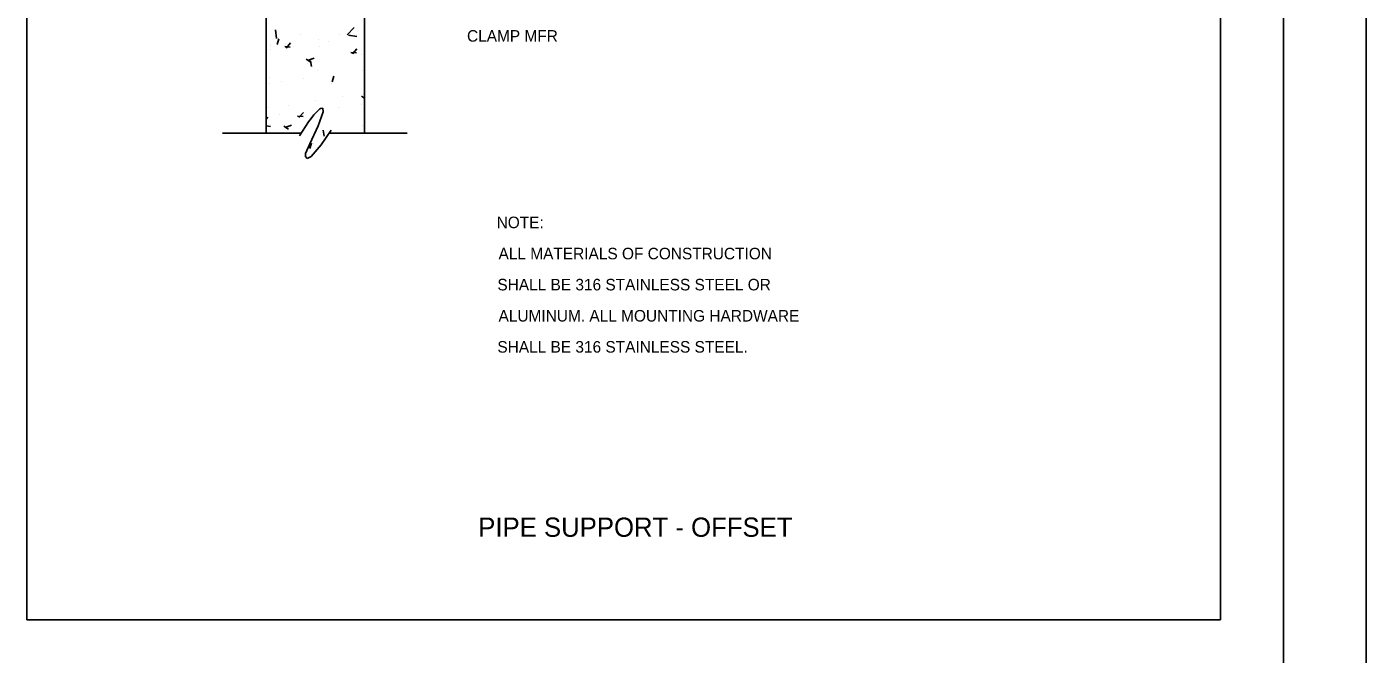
# Model space of a CAD drawing. Extents: x 2147138 to 2147698, y 2147153 to 2147515.
# Drawn here: x 2147558.3 to 2147697.7, y 2147347.7 to 2147412.9 of the extents above; entities that cross this region are included whole.
import ezdxf

# ---------------------------------------------------------------- set-up
doc = ezdxf.new("R2010")
doc.units = 0
for name, color, linetype in [('CONSTRUCTION_CLASS', 7, 'Continuous'), ('G-ANNO-TEXT-LW10', 7, 'Continuous'), ('G-ANNO-TITL', 7, 'Continuous'), ('G-DETL-LW20', 7, 'Continuous'), ('G-DETL-PATT', 7, 'Continuous'), ('PATTERN_CLASS', 7, 'Continuous')]:
    doc.layers.add(name, color=color, linetype=linetype)

msp = doc.modelspace()

# ---------------------------------------------------------------- linework, layer by layer
for p, q in [((2147587.61, 2147403.05), (2147587.89, 2147403.4)), ((2147587.89, 2147403.4), (2147588.18, 2147403.79)), ((2147588.18, 2147403.79), (2147588.48, 2147404.09)), ((2147588.48, 2147404.09), (2147588.78, 2147404.37)), ((2147589.15, 2147404.07), (2147588.62, 2147402.62)), ((2147588.78, 2147404.37), (2147588.81, 2147404.39)), ((2147588.81, 2147404.39), (2147588.85, 2147404.44)), ((2147588.85, 2147404.44), (2147589.11, 2147404.46)), ((2147589.11, 2147404.46), (2147589.15, 2147404.07)), ((2147586.86, 2147401.88), (2147578.67, 2147401.88)), ((2147586.69, 2147401.6), (2147587.61, 2147403.05)), ((2147588.62, 2147402.62), (2147587.75, 2147400.77)), ((2147588.95, 2147400.66), (2147589.98, 2147402.18)), ((2147589.78, 2147401.88), (2147597.87, 2147401.88)), ((2147587.75, 2147400.77), (2147587.31, 2147399.76)), ((2147587.91, 2147399.44), (2147588.95, 2147400.66)), ((2147587.31, 2147399.76), (2147587.29, 2147399.44)), ((2147587.29, 2147399.44), (2147587.47, 2147399.23)), ((2147587.47, 2147399.23), (2147587.91, 2147399.44))]:
    msp.add_line(p, q)
at = {"layer": 'CONSTRUCTION_CLASS'}
for p, q in [((2147697.66, 2147152.81), (2147697.66, 2147515.08)), ((2147689.06, 2147507.94), (2147689.06, 2147160.52))]:
    msp.add_line(p, q, dxfattribs=at)
at = {"layer": 'G-DETL-LW20'}
for p, q in [((2147583.21, 2147401.92), (2147583.21, 2147491.1)), ((2147593.45, 2147491.1), (2147593.45, 2147401.92))]:
    msp.add_line(p, q, dxfattribs=at)
at = {"layer": 'G-DETL-PATT'}
for p, q in [((2147591.63, 2147412.09), (2147592.37, 2147412.87)), ((2147584.28, 2147411.71), (2147584.18, 2147412.62)), ((2147584.35, 2147411.09), (2147584.54, 2147411.67)), ((2147586.77, 2147412.15), (2147586.77, 2147412.15)), ((2147588.63, 2147411.61), (2147588.63, 2147411.61)), ((2147590.8, 2147412.15), (2147590.8, 2147412.15)), ((2147591.78, 2147412.04), (2147592.64, 2147411.91)), ((2147591.9, 2147411.93), (2147591.9, 2147411.93)), ((2147583.64, 2147410.89), (2147583.64, 2147410.89)), ((2147583.64, 2147410.55), (2147583.64, 2147410.55)), ((2147583.67, 2147411.07), (2147583.67, 2147411.07)), ((2147585.15, 2147410.87), (2147585.72, 2147410.82)), ((2147585.2, 2147411.19), (2147585.2, 2147411.19)), ((2147585.3, 2147410.7), (2147585.76, 2147411.25)), ((2147586.04, 2147410.87), (2147586.04, 2147410.87)), ((2147588.79, 2147410.86), (2147588.79, 2147410.86)), ((2147589.68, 2147411.35), (2147589.68, 2147411.35)), ((2147592.03, 2147410.27), (2147592.61, 2147410.22)), ((2147592.18, 2147410.1), (2147592.64, 2147410.65)), ((2147587.39, 2147409.57), (2147587.87, 2147409.25)), ((2147587.5, 2147409.08), (2147587.5, 2147409.08)), ((2147587.53, 2147409.41), (2147588.2, 2147409.67)), ((2147587.92, 2147408.79), (2147587.81, 2147409.39)), ((2147593.1, 2147410.04), (2147593.1, 2147410.04)), ((2147593.44, 2147409.09), (2147593.44, 2147409.09)), ((2147583.52, 2147407.7), (2147583.52, 2147407.7)), ((2147587.15, 2147407.56), (2147587.15, 2147407.56)), ((2147588.51, 2147408.42), (2147588.51, 2147408.42)), ((2147590.08, 2147407.22), (2147590.27, 2147407.8)), ((2147593.22, 2147408.36), (2147593.22, 2147408.36)), ((2147583.52, 2147407.08), (2147583.52, 2147407.08)), ((2147584.86, 2147407.27), (2147584.86, 2147407.27)), ((2147589.99, 2147407.05), (2147589.99, 2147407.05)), ((2147593.32, 2147405.9), (2147593.32, 2147405.9)), ((2147585.57, 2147404.76), (2147585.57, 2147404.76)), ((2147588.39, 2147405.22), (2147588.39, 2147405.22)), ((2147590.69, 2147404.57), (2147590.69, 2147404.57)), ((2147591.17, 2147405.72), (2147591.17, 2147405.72)), ((2147593.09, 2147404.89), (2147593.09, 2147404.89)), ((2147593.13, 2147405.71), (2147593.45, 2147405.49)), ((2147593.26, 2147405.55), (2147593.45, 2147405.62)), ((2147583.21, 2147403.32), (2147583.4, 2147403.52)), ((2147583.41, 2147404.5), (2147583.41, 2147404.5)), ((2147584.63, 2147403.77), (2147584.63, 2147403.77)), ((2147586.48, 2147403.65), (2147587.05, 2147403.6)), ((2147586.63, 2147403.48), (2147587.09, 2147404.03)), ((2147583.21, 2147402.63), (2147583.66, 2147402.56)), ((2147585.06, 2147402.61), (2147585.54, 2147402.29)), ((2147585.19, 2147402.45), (2147585.86, 2147402.71)), ((2147589.25, 2147401.57), (2147589.14, 2147402.17)), ((2147593.21, 2147402.7), (2147593.21, 2147402.7)), ((2147593.24, 2147401.93), (2147593.24, 2147401.93)), ((2147593.36, 2147403.05), (2147593.45, 2147403.04)), ((2147587.74, 2147400.26), (2147587.93, 2147400.84)), ((2147588.16, 2147400.79), (2147588.16, 2147400.79))]:
    msp.add_line(p, q, dxfattribs=at)
at = {"layer": 'PATTERN_CLASS'}
for p, q in [((2147558.31, 2147503.54), (2147558.31, 2147351.27)), ((2147682.5, 2147351.27), (2147682.5, 2147503.54)), ((2147558.31, 2147351.27), (2147682.5, 2147351.27)), ((2147558.31, 2147351.27), (2147558.31, 2147351.27))]:
    msp.add_line(p, q, dxfattribs=at)

# ---------------------------------------------------------------- texts
at = {"layer": 'G-ANNO-TEXT-LW10'}
for s, p in [('CLAMP MFR', (2147604.11, 2147411.38)), ('NOTE:', (2147607.19, 2147391.99)), ('ALL MATERIALS OF CONSTRUCTION', (2147607.39, 2147388.75)), ('SHALL BE 316 STAINLESS STEEL OR', (2147607.27, 2147385.52)), ('ALUMINUM. ALL MOUNTING HARDWARE', (2147607.39, 2147382.28)), ('SHALL BE 316 STAINLESS STEEL.', (2147607.27, 2147379.05))]:
    msp.add_text(s, height=1.2, dxfattribs=at).set_placement(p)
at = {"layer": 'G-ANNO-TITL'}
msp.add_text('PIPE SUPPORT - OFFSET', height=2, dxfattribs=at).set_placement((2147605.28, 2147359.9))

doc.saveas('drawing.dxf')
